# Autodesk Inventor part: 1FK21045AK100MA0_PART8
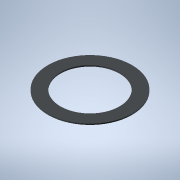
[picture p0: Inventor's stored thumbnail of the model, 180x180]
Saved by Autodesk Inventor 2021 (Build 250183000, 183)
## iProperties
Created: 2025-04
Part Number: 1FK21045AK100MA0_PART8
Material: Generic
Catalog Web Link: www.3dfindit.com
Description: -Servo synchronous motor
Document SubType Name: Modeling
Designer: psAdmin
Mass: 0.27214 g
Surface Area: 11.8752 cm^2
Volume: 0.27214 cm^3
Density: 1 g/cm^3
Appearance: PSOLRGB-212-217-219
Category: PARTsolutions
Title: 1FK21045AK100MA0_PART8
Author: Cadenas PARTsolutions
Comments: Servo synchronous motor
Sending System: PARTsolutions
Preprocessor: ST-DEVELOPER v19.3
PSOL_IDENT_0: {$CADENAS_DATA/23d-libs/siemens_ag/_cat_/e0/5f/1fk21045ak100ma0.prj},213 {VTYP=3D},{NB=1FK21045AK100
PSOL_IDENT_1: MA0_PART8},{LINA=1FK21045AK100MA0_PART8},{NN=1FK21045AK100MA0_PART8},{NOPRJ=TRUE},{DATE=19.08.2025 1
PSOL_IDENT_2: 4:01:03},{GEOMDATE=30.07.2025 02:01:57},{VERSION=},{LINEID=10},{WBVAR=},{WBNUMERIC=}  {NB=1FK21045AK
PSOL_IDENT_3: 100MA0_PART8},{LINA=1FK21045AK100MA0_PART8},{KT=DUMMY},{PREVIEW=../../../_pool_/0f/2c/p_d211_xx_0043
PSOL_IDENT_4: 8j.png},{DESCSHORT=SIMOTICS S-1FK2 HD, SINAMICS S210 3AC 400V-480V, 1.7 Nm, 6000 rpm},{DESCLONG=SIMO
PSOL_IDENT_5: TICS S-1FK2 HD servo motor M0=2.4 Nm; PN = 1.07 kW at nN=6000 rpm (380-480 V); PN = 0.75 kW at nN=30
PSOL_IDENT_6: 00 rpm (200-240 V); with holding brake; degree of protection IP64; cylindrical shaft D19x40mm; absol
PSOL_IDENT_7: ute encoder 22-bit + 12-bit multiturn (encoder AM22DQC); with OCC interface; plug size M17, rotatabl
PSOL_IDENT_8: e; SIMOTICS S-1FK2 servomotorfor a wide range of uses in industrial environments. SIMOTICS S‑1FK2 se
PSOL_IDENT_9: rvomotors are compact synchronous motors with a high dynamic performance that set themselves apart a
PSOL_IDENT_10: s a result of their high power density, degree of protection and overload capability. The motors are
PSOL_IDENT_11: available in two variants: as High Dynamic variant (highest dynamic performance as a result of the
PSOL_IDENT_12: low intrinsic moment of inertia for applications demanding a high dynamic performance with low moved
PSOL_IDENT_13: masses) - and as Compact variant (precise and stable closed-loop control for medium up to large mov
PSOL_IDENT_14: ed masses as a result of a medium intrinsic moment of inertia). SIMOTICSS‑1FK2 servomotors fully exp
PSOL_IDENT_15: loit their strengths in a system with the SINAMICSS210 frequency converter and simple connection usi
PSOL_IDENT_16: ng the one cable connection (OCC). Advantages include the short control and positioning times, fast
PSOL_IDENT_17: and precise correction of disturbing quantities as well as stable control with a high dynamic perfor
PSOL_IDENT_18: mance. The servo motors can be configured to address a wide range of requirements. For example with
PSOL_IDENT_19: and without holding brake, IP64 or IP65 degree of protection, singleturn or multiturn absolute encod
PSOL_IDENT_20: ers - to name just a few. Further, the servomotors are available in different shaft heights extendin
PSOL_IDENT_21: g from 20 to 100. A shaft sealing ring is available to achieve an IP65 degree of protection and for
PSOL_IDENT_22: subsequent mounting at the motor or as spare part. SIMOTICS - the optimum motor for each and every m
PSOL_IDENT_23: otion control application.},{INTNO=804766807114},{SUPPLIERALTNO=1FK2104-5AK10-0MA0},{MANUID=1FK21045
PSOL_IDENT_24: AK100MA0},{MANUNAME=Siemens},{MANUTYPEDESC=Synchronous motor 1FK2-HD 2,39 Nm},{AAU732=SIMOTICS},{AAO
PSOL_IDENT_25: 057=S-1FK2},{AAU734=SIMOTICS S-1FK2 HD servo motor M0=2.4 Nm; PN = 1.07 kW at nN=6000 rpm (380-480 V
PSOL_IDENT_26: ); PN = 0.75 kW at nN=3000 rpm (200-240 V); with holding brake; degree of protection IP64; cylindric
PSOL_IDENT_27: al shaft D19x40mm; absolute encoder 22-bit + 12-bit multiturn (encoder AM22DQC); with OCC interface;
PSOL_IDENT_28: plug size M17, rotatable;},{AAW338=Synchronous motor 1FK2-HD 2,39 Nm},{AAO742=SIMOTICS},{AAO663=404
PSOL_IDENT_29: 2948691236},{NOCUPEROU=1},{PRICEQUANTITY=1},{QUANTITYMIN=1},{QUANTITYINT=1},{CTN=85015100},{COO=DE},
PSOL_IDENT_30: {AAO676=1FK2104-5AK10-0MA0},{AAO677=Siemens AG},{ORDERUNIT=C62},{CONTENTUNIT=C62}
NB: 1FK21045AK100MA0_PART8
NT: Servo synchronous motor
NBSYN: $MANUID._PART8
LINA: 1FK21045AK100MA0_PART8
CATALOG: SIEMENS
PREVIEW: ../../../_pool_/0f/2c/p_d211_xx_00438j.png
DESCSHORT: SIMOTICS S-1FK2 HD, SINAMICS S210 3AC 400V-480V, 1.7 Nm, 6000 rpm
DESCLONG: SIMOTICS S-1FK2 HD servo motor M0=2.4 Nm; PN = 1.07 kW at nN=6000 rpm (380-480 V); PN = 0.75 kW at nN=3000 rpm (200-240 V); with holding brake; degree of protec
INTNO: 804766807114
SUPPLIERALTNO: 1FK2104-5AK10-0MA0
MANUID: 1FK21045AK100MA0
MANUNAME: Siemens
MANUTYPEDESC: Synchronous motor 1FK2-HD 2,39 Nm
AAU732: SIMOTICS
AAO057: S-1FK2
AAU734: SIMOTICS S-1FK2 HD servo motor M0=2.4 Nm; PN = 1.07 kW at nN=6000 rpm (380-480 V); PN = 0.75 kW at nN=3000 rpm (200-240 V); with holding brake; degree of protec
AAW338: Synchronous motor 1FK2-HD 2,39 Nm
AAO742: SIMOTICS
AAO663: 4042948691236.0
NOCUPEROU: 1
PRICEQUANTITY: 1
QUANTITYMIN: 1
QUANTITYINT: 1
CTN: 85015100
COO: DE
ARTICLENO: 1FK21045AK100MA0_PART8
BOMINFO: 1FK21045AK100MA0_PART8
CREATOR: CADENAS GmbH
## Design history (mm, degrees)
feature "2025_04_17_15_45_15_0090"
body "Solid1"
